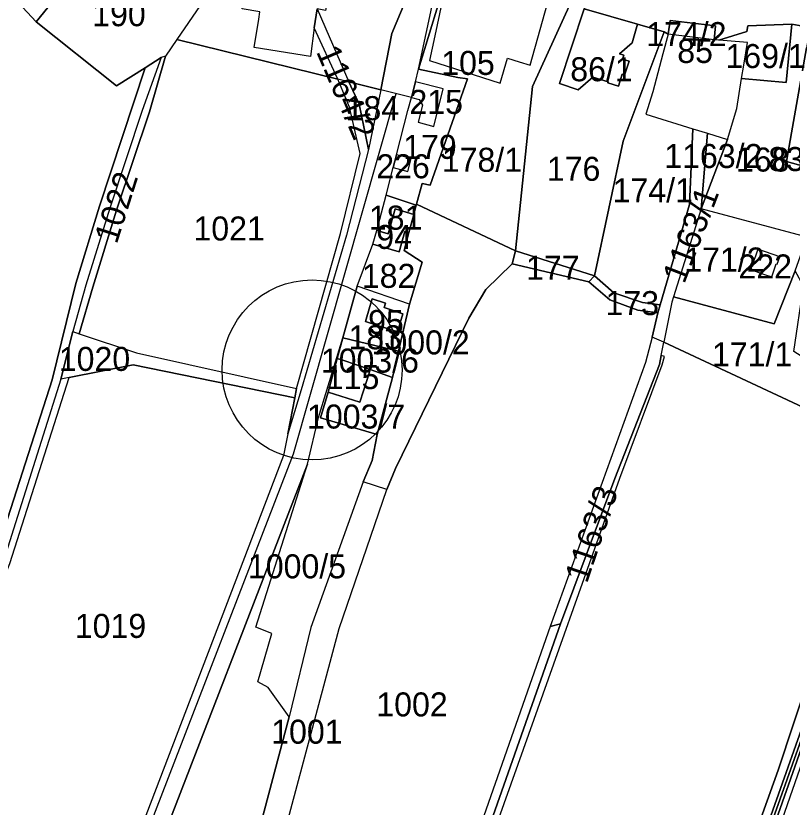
# Model space of a CAD drawing. Extents: x -623250 to -619626, y -1079612 to -1075424.
# Drawn here: x -621742.5 to -621418.9, y -1077865.3 to -1077535.8 of the extents above; entities that cross this region are included whole.
import ezdxf

# ---------------------------------------------------------------- set-up
doc = ezdxf.new("R2010")
doc.units = 0
for name, color, linetype in [('Bodové pole k revizi', 7, 'Continuous'), ('Hranice šetřená (k_ú_Džbánov - vnitřní obvod)', 7, 'Continuous'), ('Parcela nároku', 7, 'Continuous'), ('Parcelní číslo', 7, 'Continuous'), ('Silnice III_35719', 7, 'Continuous')]:
    doc.layers.add(name, color=color, linetype=linetype)

msp = doc.modelspace()

# ---------------------------------------------------------------- linework, layer by layer
at = {"layer": 'Bodové pole k revizi'}
msp.add_circle((-621618.98, -1077683.25), 37.5, dxfattribs=at)
at = {"layer": 'Hranice šetřená (k_ú_Džbánov - vnitřní obvod)'}
for p, q in [((-621734.05, -1077538.24), (-621752.84, -1077518.07)), ((-621700.52, -1077565), (-621734.05, -1077538.24)), ((-621675.33, -1077545.64), (-621680.08, -1077552.58)), ((-621608.22, -1077562.17), (-621675.33, -1077545.64)), ((-621681.9, -1077553.1), (-621688.62, -1077557.39)), ((-621680.08, -1077552.58), (-621681.9, -1077553.1)), ((-621688.62, -1077557.39), (-621700.52, -1077565)), ((-621603.65, -1077563.3), (-621608.22, -1077562.17)), ((-621590.32, -1077566.58), (-621603.65, -1077563.3)), ((-621577.62, -1077569.75), (-621590.32, -1077566.58)), ((-621579.05, -1077575.26), (-621577.62, -1077569.75)), ((-621583.82, -1077593.67), (-621579.05, -1077575.26)), ((-621585.2, -1077599.01), (-621583.82, -1077593.67)), ((-621588.19, -1077610.54), (-621585.2, -1077599.01)), ((-621591.98, -1077625.17), (-621588.19, -1077610.54)), ((-621593.71, -1077630.84), (-621591.98, -1077625.17)), ((-621600.23, -1077648.3), (-621593.71, -1077630.84)), ((-621606.15, -1077669.9), (-621600.23, -1077648.3)), ((-621608.49, -1077678.45), (-621606.15, -1077669.9)), ((-621612.35, -1077692.55), (-621608.49, -1077678.45)), ((-621615.48, -1077703.25), (-621612.35, -1077692.55)), ((-621591.87, -1077710.12), (-621615.48, -1077703.25))]:
    msp.add_line(p, q, dxfattribs=at)
msp.add_lwpolyline([(-621379.95, -1077714.81), (-621472.37, -1077671.75), (-621477.29, -1077669.61), (-621474.91, -1077659.48), (-621473.93, -1077656.14), (-621481.28, -1077655.23), (-621493.28, -1077651.08), (-621501.26, -1077644.07), (-621534.26, -1077633.61), (-621575.49, -1077614.16), (-621575.63, -1077614.69), (-621576.66, -1077618.59), (-621578.64, -1077626.08), (-621580.59, -1077633.46), (-621573.12, -1077638.43), (-621578.37, -1077655.91), (-621582.97, -1077675.43), (-621585.55, -1077686.35), (-621591.87, -1077710.12)], dxfattribs=at)
at = {"layer": 'Parcela nároku'}
for points in [[(-621708.21, -1077493.7), (-621703, -1077500.17), (-621734.05, -1077538.24), (-621752.84, -1077518.07), (-621756.42, -1077514.21), (-621787, -1077476.76), (-621790.26, -1077474.27), (-621780.8, -1077469.75), (-621762.98, -1077466.04), (-621733.65, -1077467.49), (-621728.7, -1077466.06), (-621725.91, -1077470.2), (-621725.47, -1077470.86)], [(-621689.16, -1077515.99), (-621666.98, -1077530.67), (-621665.65, -1077531.48), (-621675.33, -1077545.64), (-621680.08, -1077552.58), (-621681.9, -1077553.1), (-621688.62, -1077557.39), (-621700.52, -1077565), (-621734.05, -1077538.24), (-621703, -1077500.17), (-621694.06, -1077488.79), (-621674.31, -1077465.06), (-621673.89, -1077464.27), (-621667.71, -1077473.19), (-621699.21, -1077509.34), (-621695.56, -1077511.75)], [(-621643.11, -1077548.92), (-621641.26, -1077537.15), (-621640.79, -1077534.12), (-621648.14, -1077532.92), (-621645.67, -1077517.19), (-621642.32, -1077517.74), (-621639.15, -1077497.53), (-621611.52, -1077502.04), (-621613.43, -1077514.25), (-621610.05, -1077514.8), (-621613.34, -1077533.5), (-621616.86, -1077532.88), (-621618.1, -1077540.78), (-621619.61, -1077552.7)], [(-621570.02, -1077554.44), (-621540.57, -1077563.79), (-621537.5, -1077553.48), (-621532.75, -1077554.94), (-621528.1, -1077556.37), (-621518.79, -1077523.05), (-621530.13, -1077519.75), (-621531.8, -1077519.26), (-621525.77, -1077507.45), (-621508.19, -1077523.73), (-621527.12, -1077565.22), (-621534.26, -1077633.61), (-621575.49, -1077614.16), (-621573.12, -1077605.67), (-621569.74, -1077606.33), (-621554.16, -1077562.06), (-621558.2, -1077561.44), (-621574.58, -1077558.02), (-621561.99, -1077516.53), (-621567.79, -1077544.18)], [(-621563.38, -1077513.93), (-621561.57, -1077514.53), (-621561.99, -1077516.53), (-621574.58, -1077558.02), (-621565.12, -1077513.35)], [(-621536.83, -1077517.79), (-621538.37, -1077522.19), (-621561.57, -1077514.53), (-621561.99, -1077516.53), (-621567.79, -1077544.18), (-621570.02, -1077554.44), (-621540.57, -1077563.79), (-621537.5, -1077553.48), (-621532.75, -1077554.94), (-621528.1, -1077556.37), (-621518.79, -1077523.05), (-621530.13, -1077519.75), (-621531.8, -1077519.26)], [(-621760.82, -1077546.14), (-621757.08, -1077532.98), (-621752.84, -1077518.07), (-621734.05, -1077538.24), (-621700.52, -1077565), (-621688.62, -1077557.39), (-621707.64, -1077614.99), (-621717.4, -1077647.19), (-621727.29, -1077687.33), (-621752.14, -1077764.24), (-621804.3, -1077897.68), (-621870.37, -1077892.96), (-621848.84, -1077819.93), (-621826.8, -1077755.86), (-621795.11, -1077653.4)], [(-621491.25, -1077565.09), (-621489.79, -1077560.14), (-621488.72, -1077560.46), (-621486.86, -1077554.73), (-621489.61, -1077553.89), (-621489.07, -1077552.2), (-621490.85, -1077551.64), (-621485.61, -1077547.09), (-621483.32, -1077539.3), (-621472.27, -1077542.46), (-621489.38, -1077588.03), (-621501.26, -1077644.07), (-621534.26, -1077633.61), (-621527.12, -1077565.22), (-621508.19, -1077523.73), (-621504.04, -1077528.05), (-621505.63, -1077532.93), (-621515.9, -1077564.01), (-621508.14, -1077566.67), (-621502.05, -1077561.37), (-621495.62, -1077563.28), (-621495.76, -1077563.75)], [(-621625.49, -1077690.95), (-621607.09, -1077626.39), (-621598.99, -1077593.1), (-621603.38, -1077573.89), (-621608.22, -1077562.17), (-621618.1, -1077540.78), (-621616.86, -1077532.88), (-621603.65, -1077563.3), (-621599.43, -1077572.63), (-621595.47, -1077591.44), (-621604.63, -1077627.16), (-621623.5, -1077691.61), (-621629.04, -1077709.92), (-621626.22, -1077694.86)], [(-621495.76, -1077563.75), (-621495.62, -1077563.28), (-621502.05, -1077561.37), (-621508.14, -1077566.67), (-621515.9, -1077564.01), (-621505.63, -1077532.93), (-621483.32, -1077539.3), (-621485.61, -1077547.09), (-621490.85, -1077551.64), (-621489.07, -1077552.2), (-621489.61, -1077553.89), (-621486.86, -1077554.73), (-621488.72, -1077560.46), (-621489.79, -1077560.14), (-621491.25, -1077565.09)], [(-621470.55, -1077543.42), (-621469.81, -1077537.72), (-621450.85, -1077539.89), (-621451.4, -1077545.84)], [(-621421.37, -1077563.54), (-621419.1, -1077539.22), (-621411.47, -1077540.68), (-621412.94, -1077549.12), (-621419.12, -1077584.51), (-621421.21, -1077596.44), (-621402.8, -1077601.53), (-621412.65, -1077627.97), (-621456.87, -1077616.12), (-621445.88, -1077587.23), (-621441.98, -1077574.44), (-621439.96, -1077561.89)], [(-621437.4, -1077540), (-621419.1, -1077539.22), (-621421.37, -1077563.54), (-621439.96, -1077561.89), (-621439.07, -1077556.37), (-621437.54, -1077546.84), (-621445.96, -1077546.23), (-621449.44, -1077545.98), (-621437.76, -1077542.27)], [(-621479.96, -1077576.77), (-621460.35, -1077582.79), (-621461.67, -1077614.35), (-621473.93, -1077656.14), (-621481.28, -1077655.23), (-621493.28, -1077651.08), (-621501.26, -1077644.07), (-621489.38, -1077588.03), (-621472.27, -1077542.46), (-621470.55, -1077543.42), (-621472.76, -1077551.61), (-621477.02, -1077567.45)], [(-621700.45, -1077616.67), (-621710.34, -1077648.79), (-621716.13, -1077668.2), (-621692.14, -1077676.17), (-621625.49, -1077690.95), (-621607.09, -1077626.39), (-621598.99, -1077593.1), (-621603.38, -1077573.89), (-621608.22, -1077562.17), (-621675.33, -1077545.64), (-621680.08, -1077552.58), (-621686.79, -1077575.81)], [(-621437.54, -1077546.84), (-621445.96, -1077546.23), (-621449.44, -1077545.98), (-621451.4, -1077545.84), (-621470.55, -1077543.42), (-621472.76, -1077551.61), (-621477.02, -1077567.45), (-621479.96, -1077576.77), (-621460.35, -1077582.79), (-621454.22, -1077584.67), (-621445.88, -1077587.23), (-621441.98, -1077574.44), (-621439.96, -1077561.89), (-621439.07, -1077556.37)], [(-621419.12, -1077584.51), (-621412.94, -1077549.12), (-621402, -1077551.23), (-621403.4, -1077557.8), (-621387.79, -1077561.88), (-621390.24, -1077568.33), (-621398.43, -1077589.98), (-621402.8, -1077601.53), (-621421.21, -1077596.44)], [(-621703.3, -1077615.89), (-621713.26, -1077647.97), (-621718.74, -1077667.28), (-621716.13, -1077668.2), (-621710.34, -1077648.79), (-621700.45, -1077616.67), (-621686.79, -1077575.81), (-621680.08, -1077552.58), (-621681.9, -1077553.1), (-621689.79, -1077575.15)], [(-621574.58, -1077558.02), (-621558.2, -1077561.44), (-621554.16, -1077562.06), (-621569.74, -1077606.33), (-621573.12, -1077605.67), (-621575.49, -1077614.16), (-621575.63, -1077614.69), (-621588.19, -1077610.54), (-621585.2, -1077599.01), (-621579.12, -1077600.61), (-621577.74, -1077595.25), (-621583.82, -1077593.67), (-621579.05, -1077575.26), (-621577.62, -1077569.75), (-621574.36, -1077570.58), (-621572.99, -1077572.96), (-621574.83, -1077580.14), (-621568.29, -1077581.82), (-621564.31, -1077566.19), (-621575.93, -1077563.23)], [(-621603.65, -1077563.3), (-621590.32, -1077566.58), (-621595.47, -1077591.44), (-621599.43, -1077572.63)], [(-621575.93, -1077563.23), (-621577.62, -1077569.75), (-621574.36, -1077570.58), (-621572.99, -1077572.96), (-621574.83, -1077580.14), (-621568.29, -1077581.82), (-621564.31, -1077566.19)], [(-621460.35, -1077582.79), (-621454.22, -1077584.67), (-621456.87, -1077616.12), (-621468.32, -1077652.78), (-621469.02, -1077655.02), (-621472.37, -1077671.75), (-621477.29, -1077669.61), (-621474.91, -1077659.48), (-621473.93, -1077656.14), (-621461.67, -1077614.35)], [(-621454.22, -1077584.67), (-621445.88, -1077587.23), (-621456.87, -1077616.12)], [(-621577.74, -1077595.25), (-621583.82, -1077593.67), (-621585.2, -1077599.01), (-621579.12, -1077600.61)], [(-621591.98, -1077625.17), (-621588.19, -1077610.54), (-621575.63, -1077614.69), (-621576.66, -1077618.59), (-621584.37, -1077616.18), (-621587.33, -1077626.53)], [(-621578.64, -1077626.08), (-621576.66, -1077618.59), (-621575.63, -1077614.69), (-621575.49, -1077614.16), (-621534.26, -1077633.61), (-621535.56, -1077639), (-621546.59, -1077649.72), (-621553.71, -1077661.68), (-621584.18, -1077724.36), (-621587.82, -1077733.09), (-621597.71, -1077729.92), (-621594.01, -1077720.91), (-621591.87, -1077710.12), (-621585.55, -1077686.35), (-621582.97, -1077675.43), (-621578.37, -1077655.91), (-621573.12, -1077638.43), (-621580.59, -1077633.46)], [(-621584.37, -1077616.18), (-621576.66, -1077618.59), (-621578.64, -1077626.08), (-621580.38, -1077625.64), (-621582.75, -1077634.14), (-621593.71, -1077630.84), (-621591.98, -1077625.17), (-621587.33, -1077626.53)], [(-621412.65, -1077627.97), (-621456.87, -1077616.12), (-621468.32, -1077652.78), (-621426.47, -1077663.99), (-621417.6, -1077642.03)], [(-621580.38, -1077625.64), (-621578.64, -1077626.08), (-621580.59, -1077633.46), (-621573.12, -1077638.43), (-621578.37, -1077655.91), (-621600.23, -1077648.3), (-621593.71, -1077630.84), (-621582.75, -1077634.14)], [(-621535.56, -1077639), (-621534.26, -1077633.61), (-621501.26, -1077644.07), (-621503.65, -1077646.53)], [(-621425.51, -1077639.1), (-621425.14, -1077639.2), (-621424.07, -1077636.22), (-621433.16, -1077632.98), (-621434.2, -1077635.87), (-621435.13, -1077638.33), (-621435.91, -1077638.69), (-621436.48, -1077640.18), (-621435.77, -1077641.61), (-621434.33, -1077642.1), (-621430.43, -1077643.45), (-621427.42, -1077644.5)], [(-621424.07, -1077636.22), (-621433.16, -1077632.98), (-621434.2, -1077635.87), (-621435.13, -1077638.33), (-621435.91, -1077638.69), (-621436.48, -1077640.18), (-621435.77, -1077641.61), (-621434.33, -1077642.1), (-621430.43, -1077643.45), (-621427.42, -1077644.5), (-621425.51, -1077639.1), (-621425.14, -1077639.2)], [(-621587.82, -1077733.09), (-621584.18, -1077724.36), (-621553.71, -1077661.68), (-621546.59, -1077649.72), (-621535.56, -1077639), (-621503.65, -1077646.53), (-621494.85, -1077654.11), (-621483.29, -1077658.41), (-621474.91, -1077659.48), (-621477.29, -1077669.61), (-621480.08, -1077680.18), (-621519.83, -1077790.15), (-621581.92, -1077967.29), (-621605.8, -1077965.02), (-621621.41, -1077955.63), (-621632.68, -1077946.59), (-621643.08, -1077931.33), (-621631.05, -1077878.12), (-621607.68, -1077790.93)], [(-621503.65, -1077646.53), (-621501.26, -1077644.07), (-621493.28, -1077651.08), (-621481.28, -1077655.23), (-621473.93, -1077656.14), (-621474.91, -1077659.48), (-621483.29, -1077658.41), (-621494.85, -1077654.11)], [(-621468.32, -1077652.78), (-621469.02, -1077655.02), (-621472.37, -1077671.75), (-621379.95, -1077714.81), (-621377.39, -1077695.22), (-621386.69, -1077709.23), (-621408.45, -1077694.77), (-621405.71, -1077690.62), (-621402.58, -1077685.89), (-621410.62, -1077680.48), (-621418.22, -1077675.64), (-621414.14, -1077648.39), (-621417.6, -1077642.03), (-621426.47, -1077663.99)], [(-621600.23, -1077648.3), (-621606.15, -1077669.9), (-621582.97, -1077675.43), (-621578.37, -1077655.91)], [(-621593.95, -1077653.64), (-621588.42, -1077655.44), (-621588.92, -1077657.32), (-621581.18, -1077659.83), (-621583.43, -1077667.43), (-621596.8, -1077663.1), (-621594.9, -1077656.79)], [(-621583.43, -1077667.43), (-621581.18, -1077659.83), (-621588.92, -1077657.32), (-621588.42, -1077655.44), (-621593.95, -1077653.64), (-621594.9, -1077656.79), (-621596.8, -1077663.1)], [(-621364.39, -1077678.9), (-621360.94, -1077671.33), (-621356.07, -1077656.62), (-621361.81, -1077680.91), (-621375.21, -1077712.24), (-621395.2, -1077773.48), (-621413.63, -1077833.01), (-621448.87, -1077932.09), (-621484.15, -1078031.22), (-621531.47, -1078143.68), (-621559.31, -1078200.97), (-621633.61, -1078348.03), (-621651.3, -1078390.37), (-621666.67, -1078429.48), (-621674.85, -1078456.45), (-621678.32, -1078456.03), (-621652.48, -1078389.36), (-621636.77, -1078350.51), (-621560.48, -1078200.14), (-621532.5, -1078143.13), (-621485.18, -1078030.89), (-621450, -1077931.7), (-621414.98, -1077832.91), (-621377.7, -1077716.06)], [(-621692.14, -1077676.17), (-621625.49, -1077690.95), (-621626.22, -1077694.86), (-621693.63, -1077681.16), (-621720.21, -1077686.42), (-621723.74, -1077687.12), (-621718.74, -1077667.28), (-621716.13, -1077668.2)], [(-621620.86, -1077722.51), (-621616.33, -1077703.12), (-621606.15, -1077669.9), (-621608.49, -1077678.45), (-621612.35, -1077692.55), (-621615.48, -1077703.25), (-621591.87, -1077710.12), (-621594.01, -1077720.91), (-621597.71, -1077729.92), (-621619.49, -1077790.5), (-621628.49, -1077827.71), (-621637.34, -1077815.56), (-621641.6, -1077813.11), (-621635.74, -1077793.06), (-621642.47, -1077790.37)], [(-621606.15, -1077669.9), (-621608.49, -1077678.45), (-621606.16, -1077679.15), (-621594.83, -1077683.09), (-621585.55, -1077686.35), (-621582.97, -1077675.43)], [(-621477.29, -1077669.61), (-621480.08, -1077680.18), (-621519.83, -1077790.15), (-621515.41, -1077788.99), (-621492.8, -1077728.4), (-621474.21, -1077680.94), (-621473.46, -1077677.22), (-621472.37, -1077671.75)], [(-621608.49, -1077678.45), (-621612.35, -1077692.55), (-621599.05, -1077696.63), (-621596.07, -1077687.19), (-621594.97, -1077683.57), (-621594.83, -1077683.09), (-621606.16, -1077679.15)], [(-621720.21, -1077686.42), (-621693.63, -1077681.16), (-621626.22, -1077694.86), (-621629.04, -1077709.92), (-621630.91, -1077718.87), (-621693.66, -1077882.95), (-621777.19, -1077901.19), (-621799.13, -1077898.59), (-621745.01, -1077763.9)], [(-621596.07, -1077687.19), (-621599.05, -1077696.63), (-621612.35, -1077692.55), (-621615.48, -1077703.25), (-621591.87, -1077710.12), (-621585.55, -1077686.35), (-621594.83, -1077683.09), (-621594.97, -1077683.57)], [(-621748.3, -1077764.91), (-621801.11, -1077898.36), (-621799.13, -1077898.59), (-621745.01, -1077763.9), (-621720.21, -1077686.42), (-621723.74, -1077687.12)], [(-621536.14, -1078141.02), (-621489.42, -1078030.25), (-621424.75, -1077849.92), (-621379.95, -1077714.81), (-621377.7, -1077716.06), (-621414.98, -1077832.91), (-621450, -1077931.7), (-621485.18, -1078030.89), (-621532.5, -1078143.13), (-621560.48, -1078200.14), (-621636.77, -1078350.51), (-621652.48, -1078389.36), (-621678.32, -1078456.03), (-621682.14, -1078455.7), (-621640.24, -1078349.18), (-621601.13, -1078271)], [(-621620.86, -1077722.51), (-621687.72, -1077895.23), (-621679.96, -1077897.54), (-621678.62, -1077893.9), (-621672.96, -1077895.72), (-621696.62, -1077961.55), (-621684.9, -1077974.23), (-621682.78, -1077966.25), (-621665.46, -1077939.55), (-621641.49, -1077876.43), (-621628.49, -1077827.71), (-621637.34, -1077815.56), (-621641.6, -1077813.11), (-621635.74, -1077793.06), (-621642.47, -1077790.37)], [(-621597.71, -1077729.92), (-621619.49, -1077790.5), (-621628.49, -1077827.71), (-621641.49, -1077876.43), (-621665.46, -1077939.55), (-621643.08, -1077931.33), (-621631.05, -1077878.12), (-621607.68, -1077790.93), (-621587.82, -1077733.09)]]:
    msp.add_lwpolyline(points, close=True, dxfattribs=at)
for points in [[(-621569.52, -1077504.32), (-621585.75, -1077543.14), (-621590.32, -1077566.58), (-621595.47, -1077591.44), (-621604.63, -1077627.16), (-621623.5, -1077691.61), (-621629.04, -1077709.92), (-621630.91, -1077718.87), (-621693.66, -1077882.95)], [(-621616.86, -1077532.88), (-621603.65, -1077563.3), (-621590.32, -1077566.58), (-621585.75, -1077543.14), (-621569.52, -1077504.32)], [(-621687.72, -1077895.23), (-621620.86, -1077722.51), (-621616.33, -1077703.12), (-621606.15, -1077669.9), (-621600.23, -1077648.3), (-621593.71, -1077630.84), (-621591.98, -1077625.17), (-621588.19, -1077610.54), (-621585.2, -1077599.01), (-621583.82, -1077593.67), (-621579.05, -1077575.26), (-621577.62, -1077569.75), (-621575.93, -1077563.23), (-621574.58, -1077558.02), (-621565.12, -1077513.35)], [(-621665.65, -1077531.48), (-621675.33, -1077545.64), (-621608.22, -1077562.17), (-621618.1, -1077540.78), (-621619.61, -1077552.7), (-621643.11, -1077548.92), (-621641.26, -1077537.15), (-621640.79, -1077534.12)], [(-621411.47, -1077540.68), (-621419.1, -1077539.22), (-621437.4, -1077540), (-621437.76, -1077542.27), (-621449.44, -1077545.98), (-621451.4, -1077545.84), (-621450.85, -1077539.89), (-621469.81, -1077537.72), (-621470.55, -1077543.42), (-621472.27, -1077542.46), (-621483.32, -1077539.3), (-621505.63, -1077532.93)], [(-621804.3, -1077897.68), (-621752.14, -1077764.24), (-621727.29, -1077687.33), (-621717.4, -1077647.19), (-621707.64, -1077614.99), (-621688.62, -1077557.39), (-621681.9, -1077553.1), (-621689.79, -1077575.15), (-621703.3, -1077615.89), (-621713.26, -1077647.97), (-621718.74, -1077667.28), (-621723.74, -1077687.12), (-621748.3, -1077764.91), (-621801.11, -1077898.36)], [(-621595.12, -1078274.48), (-621557.95, -1078201.7), (-621530.38, -1078144.73), (-621482.76, -1078032.4), (-621447.54, -1077932.95), (-621412.5, -1077833.54), (-621393.67, -1077773.75), (-621374.06, -1077714.41), (-621361.81, -1077680.91), (-621356.07, -1077656.62), (-621352.61, -1077624.67), (-621351.52, -1077619.03), (-621346.96, -1077620.27), (-621351.15, -1077650.83), (-621352.43, -1077660.2), (-621359.74, -1077683.39), (-621370.61, -1077717.85), (-621410.49, -1077834.12), (-621445.17, -1077933.59), (-621480.01, -1078033.01), (-621527.76, -1078145.86), (-621554.92, -1078203.35), (-621592.05, -1078275.81)], [(-621413.47, -1078234.45), (-621340.92, -1078060.83), (-621287.56, -1077905.65), (-621260.76, -1077824.45), (-621208.08, -1077659.7), (-621214.74, -1077657.83), (-621238.69, -1077651.01), (-621258.47, -1077645.38), (-621278, -1077639.82), (-621296.82, -1077634.46), (-621331.45, -1077654.68), (-621359.74, -1077683.39), (-621370.61, -1077717.85), (-621410.49, -1077834.12), (-621445.17, -1077933.59), (-621480.01, -1078033.01), (-621527.76, -1078145.86), (-621554.92, -1078203.35), (-621592.05, -1078275.81)], [(-621706.68, -1078264.18), (-621667.8, -1078192.73), (-621644.39, -1078145.88), (-621611.75, -1078070.36), (-621595.29, -1078022.54), (-621583.38, -1077980.56), (-621575.53, -1077966.39), (-621533.15, -1077847.48), (-621490.7, -1077728.39), (-621473.08, -1077681.08), (-621472.16, -1077677.68), (-621473.46, -1077677.22), (-621472.37, -1077671.75), (-621379.95, -1077714.81), (-621424.75, -1077849.92), (-621489.42, -1078030.25), (-621536.14, -1078141.02), (-621601.13, -1078271)], [(-621706.68, -1078264.18), (-621667.8, -1078192.73), (-621644.39, -1078145.88), (-621611.75, -1078070.36), (-621595.29, -1078022.54), (-621583.38, -1077980.56), (-621575.53, -1077966.39), (-621533.15, -1077847.48), (-621490.7, -1077728.39), (-621473.08, -1077681.08), (-621472.16, -1077677.68), (-621473.46, -1077677.22), (-621474.21, -1077680.94), (-621492.8, -1077728.4), (-621515.41, -1077788.99), (-621578.15, -1077967.24), (-621584.87, -1077979.15), (-621597.61, -1078022.88), (-621614.58, -1078072.06), (-621646.53, -1078145.75), (-621670.16, -1078192.45), (-621708.86, -1078263.97)], [(-621633.61, -1078348.03), (-621559.31, -1078200.97), (-621531.47, -1078143.68), (-621484.15, -1078031.22), (-621448.87, -1077932.09), (-621413.63, -1077833.01), (-621395.2, -1077773.48), (-621375.21, -1077712.24), (-621361.81, -1077680.91), (-621374.06, -1077714.41), (-621393.67, -1077773.75), (-621412.5, -1077833.54), (-621447.54, -1077932.95), (-621482.76, -1078032.4), (-621530.38, -1078144.73), (-621557.95, -1078201.7), (-621595.12, -1078274.48)], [(-621708.86, -1078263.97), (-621670.16, -1078192.45), (-621646.53, -1078145.75), (-621614.58, -1078072.06), (-621597.61, -1078022.88), (-621584.87, -1077979.15), (-621578.15, -1077967.24), (-621515.41, -1077788.99), (-621519.83, -1077790.15), (-621581.92, -1077967.29), (-621588.84, -1077982.27), (-621600.73, -1078020.83), (-621618.53, -1078069.92), (-621649.86, -1078144.65), (-621673.38, -1078190.19), (-621712.52, -1078262.15)]]:
    msp.add_lwpolyline(points, dxfattribs=at)
at = {"layer": 'Silnice III_35719'}
for p, q in [((-621626.71, -1077718.15), (-621583.97, -1077568.16)), ((-621741.17, -1078013.99), (-621626.71, -1077718.15))]:
    msp.add_line(p, q, dxfattribs=at)

# ---------------------------------------------------------------- texts
at = {"layer": 'Parcelní číslo'}
for s, p in [('190', (-621710.64, -1077540.11)), ('174/2', (-621479.72, -1077548.41)), ('85', (-621466.8, -1077555.42)), ('169/1', (-621446.7, -1077557.53)), ('105', (-621565.17, -1077560.4)), ('86/1', (-621511.39, -1077563.03)), ('215', (-621578.43, -1077576.63)), ('184', (-621605.03, -1077579.24)), ('179', (-621581.01, -1077595.35)), ('1163/2', (-621472.21, -1077599.16)), ('178/1', (-621564.94, -1077600.74)), ('168', (-621442.34, -1077600.64)), ('83/2', (-621428.81, -1077600.43)), ('226', (-621592.24, -1077603.44)), ('176', (-621521.16, -1077604.5)), ('174/1', (-621493.73, -1077613.46)), ('181', (-621595.33, -1077624.83)), ('1021', (-621668.45, -1077629.35)), ('94', (-621592.24, -1077632.86)), ('171/2', (-621463.88, -1077642.27)), ('177', (-621529.81, -1077645.71)), ('222', (-621441.29, -1077645.16)), ('182', (-621598.26, -1077649.07)), ('173', (-621496.72, -1077660.43)), ('95', (-621595.65, -1077668.27)), ('183', (-621603.85, -1077674.65)), ('1000/2', (-621594.2, -1077676.78)), ('1020', (-621724.57, -1077683.67)), ('1003/6', (-621615.37, -1077684.36)), ('171/1', (-621452.32, -1077681.76)), ('115', (-621613.26, -1077691.24)), ('1003/7', (-621621.11, -1077707.67)), ('1000/5', (-621645.74, -1077770.05)), ('1019', (-621717.89, -1077794.85)), ('1002', (-621592.22, -1077827.55)), ('1001', (-621636.04, -1077838.91))]:
    msp.add_text(s, height=10, dxfattribs=at).set_placement(p)
for s, rotation, p in [('1164/2', 293.1724, (-621617.43, -1077550.68)), ('1022', 72.3695, (-621700.41, -1077631.16)), ('1163/1', 68.9982, (-621463.88, -1077647.74)), ('1163/3', 71.3156, (-621504.43, -1077772.46))]:
    msp.add_text(s, height=10, rotation=rotation, dxfattribs=at).set_placement(p)

doc.saveas('drawing.dxf')
